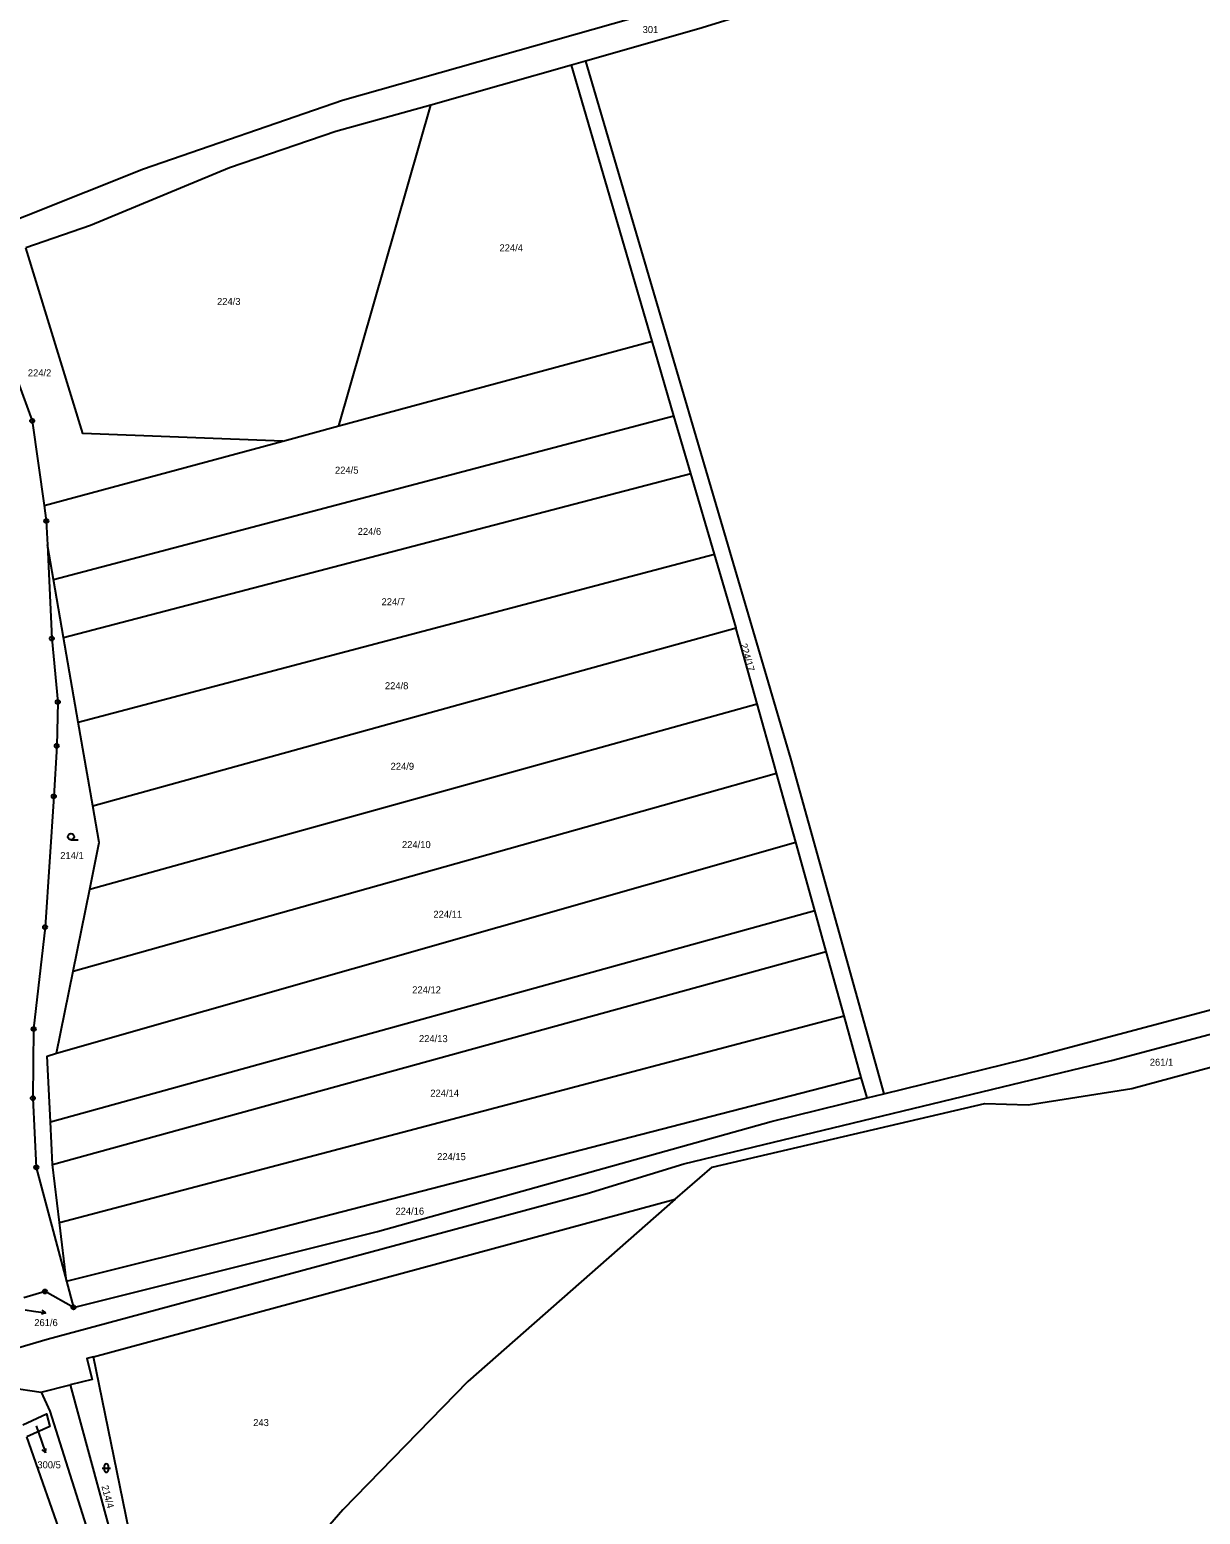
# Model space of a CAD drawing. Extents: x -779723 to -777378, y -1011169 to -1009297.
# Drawn here: x -778945.2 to -778661.4, y -1010475.7 to -1010115.8 of the extents above; entities that cross this region are included whole.
import ezdxf

# ---------------------------------------------------------------- set-up
doc = ezdxf.new("R2010")
doc.units = 0
for name, color, linetype in [('Hranice parcel', 7, 'Continuous'), ('Parcelní čísla', 7, 'Continuous'), ('Pop  PČ popisy', 7, 'Continuous'), ('Poz předměty', 7, 'Continuous'), ('Značky bodu BP', 7, 'Continuous'), ('Značky kultur', 7, 'Continuous')]:
    doc.layers.add(name, color=color, linetype=linetype)

msp = doc.modelspace()

# ---------------------------------------------------------------- linework, layer by layer
at = {"layer": 'Hranice parcel'}
for p, q in [((-778813.85, -1010124.38), (-778847.96, -1010134.1)), ((-778810.44, -1010123.41), (-778813.85, -1010124.38)), ((-778794.28, -1010191.27), (-778813.85, -1010124.38)), ((-778870.23, -1010211.82), (-778847.96, -1010134.1)), ((-778870.23, -1010211.82), (-778794.28, -1010191.27)), ((-778789, -1010209.36), (-778794.28, -1010191.27)), ((-778939.44, -1010249.05), (-778789, -1010209.36)), ((-778883.82, -1010215.5), (-778870.23, -1010211.82)), ((-778784.9, -1010223.38), (-778789, -1010209.36)), ((-778941.69, -1010231.16), (-778883.82, -1010215.5)), ((-778936.98, -1010263.15), (-778784.9, -1010223.38)), ((-778779.19, -1010242.93), (-778784.9, -1010223.38)), ((-778939.44, -1010249.05), (-778940.9, -1010240.67)), ((-778933.41, -1010283.65), (-778779.19, -1010242.93)), ((-778773.96, -1010260.81), (-778779.19, -1010242.93)), ((-778936.98, -1010263.15), (-778939.44, -1010249.05)), ((-778929.88, -1010303.92), (-778773.96, -1010260.81)), ((-778933.41, -1010283.65), (-778936.98, -1010263.15)), ((-778930.63, -1010324.14), (-778768.84, -1010279.18)), ((-778929.88, -1010303.92), (-778933.41, -1010283.65)), ((-778759.49, -1010312.74), (-778764.15, -1010296.01)), ((-778938.68, -1010363.9), (-778759.49, -1010312.74)), ((-778754.87, -1010329.33), (-778759.49, -1010312.74)), ((-778934.65, -1010344), (-778930.63, -1010324.14)), ((-778940.18, -1010380.55), (-778754.87, -1010329.33)), ((-778752.11, -1010339.25), (-778754.87, -1010329.33)), ((-778939.67, -1010390.9), (-778752.11, -1010339.25)), ((-778747.77, -1010354.85), (-778752.11, -1010339.25)), ((-778938.68, -1010363.9), (-778934.65, -1010344)), ((-778937.98, -1010404.92), (-778747.77, -1010354.85)), ((-778743.6, -1010369.82), (-778747.77, -1010354.85)), ((-778742.19, -1010374.76), (-778743.6, -1010369.82)), ((-778742.19, -1010374.76), (-778738.09, -1010373.73)), ((-778939.67, -1010390.9), (-778940.18, -1010380.55)), ((-778937.98, -1010404.92), (-778939.67, -1010390.9)), ((-778929.7, -1010437.49), (-778788.69, -1010399.25)), ((-778936.31, -1010419.18), (-778937.98, -1010404.92)), ((-778936.31, -1010419.18), (-778934.57, -1010425.53)), ((-778950.06, -1010444.91), (-778942.45, -1010446.06)), ((-778942.45, -1010446.06), (-778935.36, -1010444.3)), ((-778927.24, -1010510.3), (-778945.86, -1010456.94))]:
    msp.add_line(p, q, dxfattribs=at)
for points in [[(-778554.23, -1010046.82), (-778561.81, -1010044.31), (-778580.85, -1010045.72), (-778594.64, -1010047.86), (-778622.94, -1010059.11), (-778684.92, -1010081.46), (-778712.5, -1010092.84), (-778729.23, -1010099), (-778782.95, -1010115.6), (-778810.44, -1010123.41)], [(-778981.44, -1010170.24), (-778960.05, -1010166.44), (-778917.58, -1010149.52), (-778869.36, -1010132.88), (-778766.08, -1010103.5), (-778721.06, -1010087.16), (-778695.97, -1010079.62), (-778608.15, -1010047.05)], [(-778810.44, -1010123.41), (-778760.75, -1010292.49), (-778738.09, -1010373.73)], [(-778847.96, -1010134.1), (-778870.96, -1010140.49), (-778896.72, -1010149.28), (-778930.42, -1010163.26), (-778946.12, -1010168.67)], [(-778883.82, -1010215.5), (-778932.35, -1010213.67), (-778946.12, -1010168.67)], [(-778970.48, -1010181.53), (-778969.19, -1010181.68), (-778956.78, -1010189.07), (-778948.1, -1010201.08), (-778944.59, -1010210.6), (-778941.69, -1010231.16)], [(-778941.69, -1010231.16), (-778941.17, -1010234.88), (-778940.9, -1010240.67)], [(-778940.9, -1010240.67), (-778939.84, -1010263.37), (-778938.39, -1010278.77), (-778938.64, -1010289.39), (-778939.36, -1010301.65), (-778941.47, -1010333.34), (-778944.25, -1010358.02), (-778944.43, -1010374.8), (-778943.59, -1010391.58), (-778936.31, -1010419.18)], [(-778768.84, -1010279.18), (-778773.89, -1010261.06), (-778773.96, -1010260.81)], [(-778764.15, -1010296.01), (-778764.72, -1010293.95), (-778768.84, -1010279.18)], [(-778934.65, -1010344), (-778791.6, -1010303.74), (-778764.15, -1010296.01)], [(-778738.09, -1010373.73), (-778703.98, -1010365.37), (-778650.77, -1010351.2), (-778603.44, -1010337.58), (-778573.36, -1010328.79), (-778550.31, -1010321.04), (-778500.81, -1010301.69)], [(-778930.63, -1010324.14), (-778928.34, -1010312.81), (-778929.88, -1010303.92)], [(-778788.69, -1010399.25), (-778779.77, -1010391.5), (-778713.61, -1010376.07), (-778703.11, -1010376.44), (-778678, -1010372.43), (-778652.28, -1010365.5), (-778598.81, -1010348.7)], [(-778940.18, -1010380.55), (-778940.96, -1010364.6), (-778938.68, -1010363.9)], [(-778936.31, -1010419.18), (-778891.25, -1010407.94), (-778743.6, -1010369.82)], [(-778934.57, -1010425.53), (-778860.91, -1010407.13), (-778765.47, -1010380.48), (-778742.19, -1010374.76)], [(-778788.69, -1010399.25), (-778838.99, -1010443.52), (-778869.31, -1010474.62), (-778908.34, -1010519.61)], [(-778934.57, -1010425.53), (-778941.48, -1010421.68), (-778946.64, -1010423.24)], [(-778929.7, -1010437.49), (-778931.37, -1010437.94), (-778930.03, -1010442.98), (-778935.36, -1010444.3)], [(-778908.34, -1010519.61), (-778911.59, -1010510.13), (-778921.17, -1010479.33), (-778929.7, -1010437.49)], [(-778942.45, -1010446.06), (-778940.29, -1010450.68), (-778929.57, -1010484.72), (-778918, -1010510.77), (-778913.36, -1010522.39)], [(-778935.36, -1010444.3), (-778923.56, -1010487.7), (-778905.58, -1010527.64)], [(-778946.9, -1010453.97), (-778941.12, -1010451.33), (-778940.34, -1010454.4), (-778945.86, -1010456.94)]]:
    msp.add_lwpolyline(points, dxfattribs=at)
at = {"layer": 'Pop  PČ popisy'}
for p, q in [((-778946.3, -1010426.12), (-778944.25, -1010426.4)), ((-778944.25, -1010426.4), (-778941.28, -1010426.82)), ((-778941.28, -1010426.82), (-778942.34, -1010427.17)), ((-778941.28, -1010426.82), (-778942.2, -1010426.18)), ((-778943.64, -1010454.24), (-778942.37, -1010457.97)), ((-778942.37, -1010457.97), (-778941.39, -1010460.81)), ((-778941.39, -1010460.81), (-778942.19, -1010460.02)), ((-778941.39, -1010460.81), (-778941.25, -1010459.7))]:
    msp.add_line(p, q, dxfattribs=at)
at = {"layer": 'Poz předměty'}
for p, q in [((-778682.94, -1010365.64), (-778610.59, -1010346.52)), ((-778786.59, -1010390.75), (-778682.94, -1010365.64)), ((-778810.01, -1010397.92), (-778786.59, -1010390.75)), ((-778940.99, -1010433.26), (-778810.01, -1010397.92)), ((-779042.85, -1010463.08), (-778940.99, -1010433.26))]:
    msp.add_line(p, q, dxfattribs=at)
at = {"layer": 'Značky bodu BP'}
for centre, radius in [((-778944.59, -1010210.6), 0.5), ((-778944.59, -1010210.6), 0.0303), ((-778941.17, -1010234.88), 0.5), ((-778941.17, -1010234.88), 0.0303), ((-778939.84, -1010263.37), 0.5), ((-778939.84, -1010263.37), 0.0303), ((-778938.39, -1010278.77), 0.5), ((-778938.39, -1010278.77), 0.0303), ((-778938.64, -1010289.39), 0.5), ((-778938.64, -1010289.39), 0.0303), ((-778939.36, -1010301.65), 0.5), ((-778939.36, -1010301.65), 0.0303), ((-778941.47, -1010333.34), 0.5), ((-778941.47, -1010333.34), 0.0303), ((-778944.25, -1010358.02), 0.5), ((-778944.25, -1010358.02), 0.0303), ((-778944.43, -1010374.8), 0.5), ((-778944.43, -1010374.8), 0.0303), ((-778943.59, -1010391.58), 0.5), ((-778943.59, -1010391.58), 0.0303), ((-778941.48, -1010421.68), 0.5), ((-778941.48, -1010421.68), 0.0303), ((-778934.57, -1010425.53), 0.5), ((-778934.57, -1010425.53), 0.0303)]:
    msp.add_circle(centre, radius, dxfattribs=at)
at = {"layer": 'Značky kultur'}
for p, q in [((-778935.2, -1010312.17), (-778933.45, -1010312.17)), ((-778927.13, -1010463.97), (-778927.13, -1010464.97)), ((-778926.13, -1010464.97), (-778926.13, -1010463.97)), ((-778927.63, -1010464.47), (-778925.63, -1010464.47))]:
    msp.add_line(p, q, dxfattribs=at)
msp.add_circle((-778935.2, -1010311.42), 0.75, dxfattribs=at)
for centre, start, end in [((-778926.63, -1010463.97), 0, 180), ((-778926.63, -1010464.97), 180, 359.9879)]:
    msp.add_arc(centre, 0.5, start, end, dxfattribs=at)

# ---------------------------------------------------------------- texts
at = {"layer": 'Parcelní čísla'}
for s, p in [('301', (-778796.6, -1010116.6)), ('224/4', (-778831.3, -1010169.51)), ('224/3', (-778899.78, -1010182.52)), ('224/2', (-778945.65, -1010199.83)), ('224/5', (-778871.18, -1010223.41)), ('224/6', (-778865.68, -1010238.26)), ('224/7', (-778859.9, -1010255.31)), ('224/8', (-778859.08, -1010275.67)), ('224/9', (-778857.7, -1010295.2)), ('224/10', (-778854.94, -1010314.18)), ('214/1', (-778937.79, -1010316.83)), ('224/11', (-778847.33, -1010331.08)), ('224/12', (-778852.46, -1010349.39)), ('224/13', (-778850.82, -1010361.22)), ('261/1', (-778673.65, -1010366.94)), ('224/14', (-778848.07, -1010374.43)), ('224/15', (-778846.42, -1010389.83)), ('224/16', (-778856.53, -1010403.03)), ('261/6', (-778944.09, -1010430.06)), ('243', (-778891.01, -1010454.3)), ('300/5', (-778943.34, -1010464.53))]:
    msp.add_text(s, height=1.7, dxfattribs=at).set_placement(p)
for s, rotation, p in [('224/17', 286, (-778772.96, -1010264.83)), ('214/4', 285, (-778927.82, -1010468.89))]:
    msp.add_text(s, height=1.7, rotation=rotation, dxfattribs=at).set_placement(p)

doc.saveas('drawing.dxf')
